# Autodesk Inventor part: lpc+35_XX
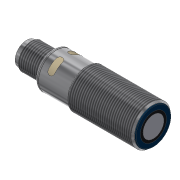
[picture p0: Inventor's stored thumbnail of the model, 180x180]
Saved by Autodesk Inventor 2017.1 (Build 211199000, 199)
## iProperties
Shininess: 20.0
Length Units: 11269
Angle Units: 11279
Time Units: 11290
Mass Units: 11283
Length Display Precision: 2
Angle Display Precision: 2
Part Number: lpc+35_XX
Material: Nichtrostender Stahl - 440C
Document SubType Name: Modellieren
Description: Ipc-25 /CXX/M18
Checked By: Alves
Created: 2005-08
Designer: Ohle
Manufacturer: Standard
Standards Organization: Custom
Appearance: Aluminium - poliert
Density: 0.0
Volumn: 0.0
Area: 0.0
PropertySet Name: Model Information
Control State: 0
Master: False
Checked Out: False
BESTELLNUMMER: Ipc-25 /CXX/M18
ME: ST
Title: Ipc Sensoren
Author: Ohle
Comments: keine Bemerkung
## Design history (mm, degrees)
sketch "Skizze10"
  geometry: L1 (-48.5, 0)-(1.5, 0); L2 (-44.5, 6.5)-(-44.5, 7.25); L3 (-45.9, 8)-(-45.9, 8); L4 (-28.75, 9)-(0.25, 9); L5 (1.5, 7.95)-(1.5, 6); L6 (1.49, 6)-(1.49, 4.8); L7 (1.5, 4.8)-(1.5, 0); L8 (1.5, 0)-(-81.71, 0); L9 (1.142, 8.25)-(1.142, 8.25); L10 (-29.5, 8.25)-(-28.75, 9); L11 (1, 8.25)-(0.25, 9); L12 (-56, 6)-(-45, 6); L13 (-42.9, 8.25)-(-29.5, 8.25); L14 (-56.5, 4.5)-(-48.5, 4.5); L15 (-48.5, 0)-(-48.5, 4.5); L16 (-43, 8.25)-(-43.5, 8.25); L17 (1, 8.25)-(1, 8.25); L18 (-45, 6)-(-44.5, 6.5); L19 (-56.5, 5.5)-(-56.5, 4.5); L20 (-56.5, 5.5)-(-56, 6); L21 (-43, 8.25)-(-43, 8.15); L22 (-43, 8.15)-(-42.9, 8.15); L23 (-42.9, 8.15)-(-42.9, 8.25); L24 (1.49, 4.8)-(1.5, 4.8); L25 (1, 8.25)-(1.2, 8.25); L26 (1.49, 6)-(1.5, 6); A1 r 1 centre (-43.5, 7.25) between (-43.5, 8.25) and (-44.5, 7.25); A2 r 0.3 centre (1.2, 7.95) between (1.5, 7.95) and (1.2, 8.25); 3 further points
  constraints: 52 end point, 7 parallel, 6 point on line, 4 perpendicular, 4 point on circle, 4 tangent, 2 centre point, 1 collinear, 1 horizontal
  dimensions: "d138" = 9 distance between parallel lines of L4 L8; "d164" = 1.5 distance from line of point (0, 0) L5; "d171" = 4.5 distance between parallel lines of L14 L1; "d250" = 0.75 distance from line of L11.start L4; "d252" = 6 distance from line of L8 L5.end; "d256" = 45 deg angle of L4 L10; "d257" = 8.25 distance between parallel lines of L8 L13; "d263" = 8.25 distance between parallel lines of L8 L16; "d266" = 12 distance from line of L2 L19.start; "d269" = 6 distance between parallel lines of L8 L12; "d289" = 135 deg angle of L11 L4; "d290" = 0.5 horizontal distance of L12.end L2.start; "d291" = 45 deg angle of L18 L12 (derived); "d293" = 0.5 horizontal distance of L19.start L12.start; "d294" = 45 deg angle of L20 L12 (derived); "d295" = 8 distance of L14.start L14.end; "d296" = 1.5 distance of L16.start point (-44.5, 8.25); "d297" = 0.1 distance of L21.end L22.end; "d298" = 8.15 distance between parallel lines of L22 L1; "d299" = 15 distance from line of L10.start L2; "d300" = 1 radius of A1; "d331" = 4.8 distance between parallel lines of L1 L24; "d333" = 0.01 distance between parallel lines of L7 L6; "d334" = 0.3 radius of A2; "d335" = 0.5 distance from line of L5 L11.start; "d336" = 0.01 distance between parallel lines of L6 L5; "d337" = 30.5 distance of L10.start L11.start
revolve "Grundkörper pico+" sketch "Skizze10" stored, may be unused: angle "d168" = 90 deg
feature "Gewinde M12" dims "d174" = 10, "d175" = 0
feature "Gewinde M 18" dims "d179" = 10, "d180" = 0
workplane "Arbeitsebene1"
workplane "Arbeitsebene2"
sketch "Skizze13"
  geometry: L1 (-3.409, -3.409)-(3.61, 3.61); L2 (-3.439, 3.439)-(4.105, -4.105); L3 (-12.6, 0)-(12.6, 0) reference; C1 r 0.5 at (2.121, -2.121); C2 r 0.5 at (2.121, 2.121); C3 r 0.5 at (-2.121, 2.121); C4 r 0.5 at (-2.121, -2.121); C5 r 4.5 at (0, 0) reference; C6 r 0.5 at (0, 0); A1 r 3 centre (0, 0) between (-2.121, 2.121) and (2.121, 2.121); 2 further points
  constraints: 6 centre point, 6 point on line, 4 coincident, 4 end point, 4 equal radius, 4 point on circle, 1 horizontal alignment, 1 perpendicular
  dimensions: "d208" = 1 diameter of C3; "d209" = 6 diameter of A1
extrude "Pole" join sketch "Skizze13" distance "d212" = 7; taper "d213" = 0 deg
fillet "Rundung Pole" dims "d214" = 0.5
sketch "Skizze14"
  geometry: C1 r 0.5 at (0, -4.5); A1 r 4.5 centre (0, 0) between (4.435, -0.762) and (4.435, 0.762); A2 r 4.5 centre (0, 0) between (0, 4.5) and (0.499, 4.472) reference; A3 r 0.5 centre (0, 4.5) between (-0.499, 4.472) and (0.499, 4.472); 3 further points
  constraints: 9 point on circle, 3 centre point, 3 coincident, 1 horizontal alignment, 1 vertical alignment
  dimensions: "d215" = 9 diameter of A1; "d280" = 1 diameter of A3; "d330" = 1 diameter of C1
extrude "Verdrehsicherung" join sketch "Skizze14" distance "d217" = 7; taper "d218" = 0 deg
sketch "Skizze18"
  geometry: C1 r 7.25 at (0, 0) reference; C2 r 1 at (-8.15, 0)
  constraints: 1 centre point, 1 horizontal alignment
  dimensions: "d328" = 2 diameter of C2; "d329" = 8.15 distance of C1.centre C2.centre
extrude "Bohrung Ausrichtung" cut sketch "Skizze18" distance "d316" = 0.75; taper "d317" = 0 deg
workplane "Arbeitsebene4"
sketch "Skizze19"
  geometry: L1 (-44.5, 0)-(-30.18, 0); L2 (-40.2, -7.5)-(-40.2, -3); L3 (-37.2, -7.5)-(-37.2, -3); L4 (-37.2, 3)-(-37.2, 7.5); L5 (-40.2, 3)-(-40.2, 7.5); A1 r 1.5 centre (-38.7, 3) between (-37.2, 3) and (-40.2, 3); A2 r 1.5 centre (-38.7, -3) between (-40.2, -3) and (-37.2, -3); A3 r 1.5 centre (-38.7, 7.5) between (-37.2, 7.5) and (-40.2, 7.5); A4 r 1.5 centre (-38.7, -7.5) between (-40.2, -7.5) and (-37.2, -7.5); 4 further points; 1 other entity
  constraints: 10 end point, 8 point on circle, 8 tangent, 4 centre point, 3 equal radius, 2 vertical alignment, 1 horizontal, 2 other
  dimensions: "d319" = 3 diameter of A2; "d320" = 6 distance of A2.centre A1.centre; "d321" = 4.5 distance of A1.centre A3.centre; "d322" = 4.5 distance of A4.centre A2.centre; "d323" = 3 distance from line of A2.centre L1; "d324" = 5.8 dimension on A1.centre; "d325" = 5.8 dimension on A2.centre
feature "Prägen LED-Fenster" sketch "Skizze19" dims "d326" = 0.01, "d327" = 0
sketch "Skizze20"
  geometry: C1 r 5.5 at (0, 0); C2 r 4.5 at (0, 0); C3 r 4.15 at (0, 0); C4 r 5.25 at (0, 0); 2 further points
  constraints: 4 centre point
  dimensions: "d338" = 8.3 diameter of C3; "d339" = 10.5 diameter of C4
extrude "Extrusion5" join sketch "Skizze20" distance "d340" = 0.2; taper "d341" = 0 deg
sketch "Skizze21"
  geometry: C1 r 5.25 at (0, 0) reference; C2 r 10.117 at (0, 0); 1 further point
  constraints: 1 centre point
extrude "Extrusion6" cut sketch "Skizze21" distance "d342" = 1.8; taper "d343" = 0 deg
chamfer "Fase2" distance "d344" = 0.75; stored, may be unused: second distance "d345" = 2, angle "d346" = 30 deg
node "Volumenkörper1"
node "Volumenkörper"
node "Flächenkörper"
other parameters: "d10" = 14, "d73" = -35, "d130" = 0.2, "d207" = -95.5, "d318" = 8.25
